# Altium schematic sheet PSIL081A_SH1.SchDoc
size 431 x 279 mm; Date: Not shown in title block; ApprovedBy: Not shown in title block; CheckedBy: Not shown in title block; Author: Not shown in title block; CompanyName: Not shown in title block; Engineer: Not shown in title block; Organization: Not shown in title block; Address1: Not shown in title block; Address2: Not shown in title block; Address3: Not shown in title block; Address4: Not shown in title block; DocumentNumber: 1; Revision: Use project parameter SCH_Rev; SheetNumber: 1; SheetTotal: 5; PageSetup: Record=PageOptions¦CenterHorizontal=True¦CenterVertical=True¦PrintScale=1.00¦XCorrection=1.00¦YCorrection=1.00¦PrintKind=0¦BorderSize=5000000¦LeftOffset=0¦BottomOffset=0¦Orientation=2¦PaperLength=1000¦PaperWidth=1000¦Scale=100¦PaperSource=15¦PrintQuality=600¦MediaType=1¦DitherType=10¦PaperKind=Letter¦PrintScaleMode=1
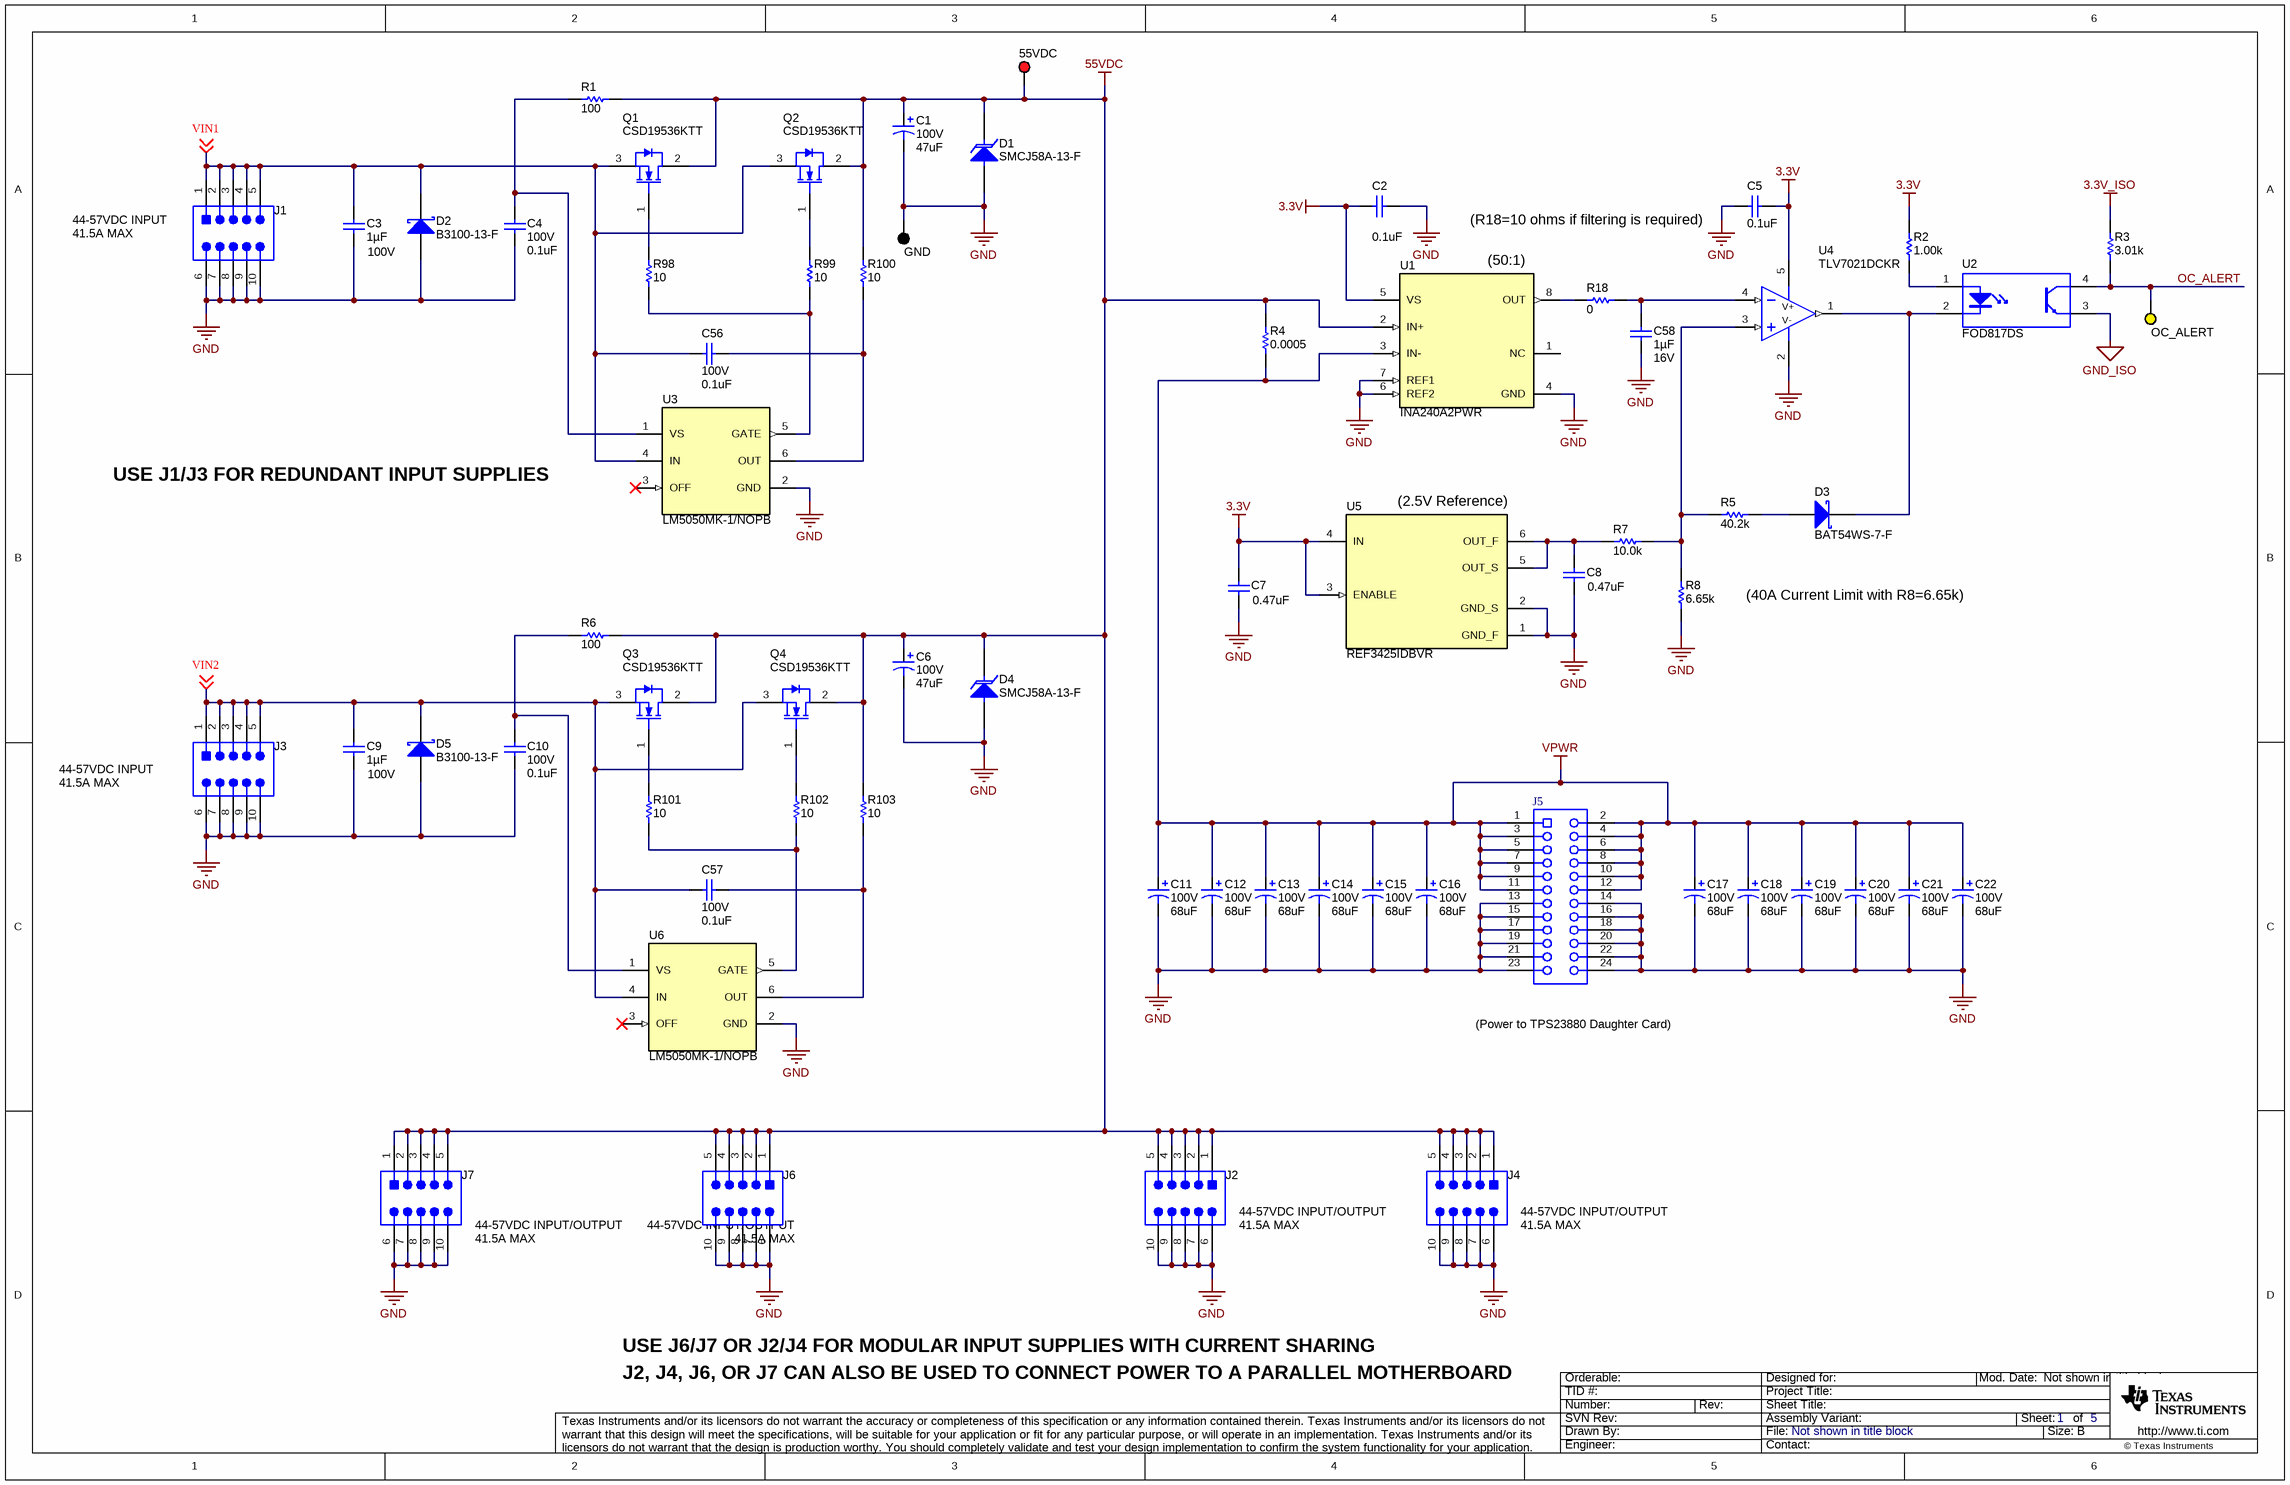
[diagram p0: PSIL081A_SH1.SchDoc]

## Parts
C1  VDC_V: 100V  ValueDisplayed: 47uF  [SM_RADIAL_H13]  (hidden comment: EEV-FK2A470Q)
C2  ValueDisplayed: 0.1uF  [0603]  (hidden comment: 885012206046)
C3  ValueDisplayed: 1µF  VDC_V: 100V  [1206]  (hidden comment: 12061C105KAT2A)
C4  VDC_V: 100V  ValueDisplayed: 0.1uF  [0805_HV]  (hidden comment: C2012X7R2A104K125AA)
C5  ValueDisplayed: 0.1uF  [0603]  (hidden comment: 885012206046)
C6  VDC_V: 100V  ValueDisplayed: 47uF  [SM_RADIAL_H13]  (hidden comment: EEV-FK2A470Q)
C7  ValueDisplayed: 0.47uF  [0603]  (hidden comment: GCM188R71C474KA55D)
C8  ValueDisplayed: 0.47uF  [0603]  (hidden comment: GCM188R71C474KA55D)
C9  ValueDisplayed: 1µF  VDC_V: 100V  [1206]  (hidden comment: 12061C105KAT2A)
C10  VDC_V: 100V  ValueDisplayed: 0.1uF  [0805_HV]  (hidden comment: C2012X7R2A104K125AA)
C11  VDC_V: 100V  ValueDisplayed: 68uF  [SM_RADIAL_H13]  (hidden comment: EEV-FK2A680Q)
C12  VDC_V: 100V  ValueDisplayed: 68uF  [SM_RADIAL_H13]  (hidden comment: EEV-FK2A680Q)
C13  VDC_V: 100V  ValueDisplayed: 68uF  [SM_RADIAL_H13]  (hidden comment: EEV-FK2A680Q)
C14  VDC_V: 100V  ValueDisplayed: 68uF  [SM_RADIAL_H13]  (hidden comment: EEV-FK2A680Q)
C15  VDC_V: 100V  ValueDisplayed: 68uF  [SM_RADIAL_H13]  (hidden comment: EEV-FK2A680Q)
C16  VDC_V: 100V  ValueDisplayed: 68uF  [SM_RADIAL_H13]  (hidden comment: EEV-FK2A680Q)
C17  VDC_V: 100V  ValueDisplayed: 68uF  [SM_RADIAL_H13]  (hidden comment: EEV-FK2A680Q)
C18  VDC_V: 100V  ValueDisplayed: 68uF  [SM_RADIAL_H13]  (hidden comment: EEV-FK2A680Q)
C19  VDC_V: 100V  ValueDisplayed: 68uF  [SM_RADIAL_H13]  (hidden comment: EEV-FK2A680Q)
C20  VDC_V: 100V  ValueDisplayed: 68uF  [SM_RADIAL_H13]  (hidden comment: EEV-FK2A680Q)
C21  VDC_V: 100V  ValueDisplayed: 68uF  [SM_RADIAL_H13]  (hidden comment: EEV-FK2A680Q)
C22  VDC_V: 100V  ValueDisplayed: 68uF  [SM_RADIAL_H13]  (hidden comment: EEV-FK2A680Q)
C56  VDC_V: 100V  ValueDisplayed: 0.1uF  [0805_HV]  (hidden comment: C2012X7R2A104K125AA)
C57  VDC_V: 100V  ValueDisplayed: 0.1uF  [0805_HV]  (hidden comment: C2012X7R2A104K125AA)
C58  Cap_F: 1µF  VDC_V: 16V  [0603]  (hidden comment: GCM188R71C105KA64D)
D1  SMCJ58A-13-F  [SMC]
D2  B3100-13-F  [SMC]
D3  BAT54WS-7-F  [SOD-323]
D4  SMCJ58A-13-F  [SMC]
D5  B3100-13-F  [SMC]
J1  1723161310  [Molex_1723161310]  (value not drawn)
J2  1723161310  [Molex_1723161310]  (value not drawn)
J3  1723161310  [Molex_1723161310]  (value not drawn)
J4  1723161310  [Molex_1723161310]  (value not drawn)
J5  SSW-112-21-G-D  [Samtec_SSW-112-01-x-D]  (value not drawn)
J6  1723161310  [Molex_1723161310]  (value not drawn)
J7  1723161310  [Molex_1723161310]  (value not drawn)
Q1  CSD19536KTT  [KTT0002A]
Q2  CSD19536KTT  [KTT0002A]
Q3  CSD19536KTT  [KTT0002A]
Q4  CSD19536KTT  [KTT0002A]
R1  ValueDisplayed: 100  [0603]  (hidden comment: CRCW0603100RJNEA)
R2  ValueDisplayed: 1.00k  [0402]  (hidden comment: CRCW04021K00FKED)
R3  ValueDisplayed: 3.01k  [0402]  (hidden comment: CRCW04023K01FKED)
R4  ValueDisplayed: 0.0005  [HCS_2512_122]  (hidden comment: HCS2512FTL500)
R5  ValueDisplayed: 40.2k  [0402]  (hidden comment: CRCW040240K2FKED)
R6  ValueDisplayed: 100  [0603]  (hidden comment: CRCW0603100RJNEA)
R7  ValueDisplayed: 10.0k  [0402]  (hidden comment: CRCW040210K0FKED)
R8  ValueDisplayed: 6.65k  [0402]  (hidden comment: CRCW04026K65FKED)
R18  ValueDisplayed: 0  [0402]  (hidden comment: ERJ-2GE0R00X)
R98  ValueDisplayed: 10  [0603]  (hidden comment: CRCW060310R0JNEA)
R99  ValueDisplayed: 10  [0603]  (hidden comment: CRCW060310R0JNEA)
R100  ValueDisplayed: 10  [0603]  (hidden comment: CRCW060310R0JNEA)
R101  ValueDisplayed: 10  [0603]  (hidden comment: CRCW060310R0JNEA)
R102  ValueDisplayed: 10  [0603]  (hidden comment: CRCW060310R0JNEA)
R103  ValueDisplayed: 10  [0603]  (hidden comment: CRCW060310R0JNEA)
TP1  55VDC  [Keystone5000]
TP2  GND  [Keystone5001]
TP3  OC_ALERT  [Keystone5004]
U1  INA240A2PWR  [PW0008A_L]
U2  FOD817DS  [N04C]
U3  LM5050MK-1/NOPB  [DDC0006A_N]
U4  TLV7021DCKR  [DCK0005A_N]
U5  REF3425IDBVR  [DBV0006A_N]
U6  LM5050MK-1/NOPB  [DDC0006A_N]

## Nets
3.3V: C2.2 C5.2 C7.2 R2.1 U1.5(VS) U4.5(V+) U5.3(ENABLE) U5.4(IN)
3.3V_ISO: R3.1
55VDC: C1.1(+) C6.1(+) D1.1(K) D4.1(K) J2.1 J2.2 J2.3 J2.4 J2.5 J4.1 J4.2 J4.3 J4.4 J4.5 J6.1 J6.2 J6.3 J6.4 J6.5 J7.1 J7.2 J7.3 J7.4 J7.5 Q1.2(D) Q2.2(D) Q3.2(D) Q4.2(D) R1.2 R4.2 R6.2 R100.1 R103.1 TP1.1 U1.2(IN+)
GND: C1.2(-) C2.1 C3.1 C4.2 C5.1 C6.2(-) C7.1 C8.1 C9.1 C10.2 C11.2(-) C12.2(-) C13.2(-) C14.2(-) C15.2(-) C16.2(-) C17.2(-) C18.2(-) C19.2(-) C20.2(-) C21.2(-) C22.2(-) C58.1 D1.2(A) D2.2(A) D4.2(A) D5.2(A) J1.6 J1.7 J1.8 J1.9 J1.10 J2.6 J2.7 J2.8 J2.9 J2.10 J3.6 J3.7 J3.8 J3.9 J3.10 J4.6 J4.7 J4.8 J4.9 J4.10 J5.13 J5.14 J5.15 J5.16 J5.17 J5.18 J5.19 J5.20 J5.21 J5.22 J5.23 J5.24 J6.6 J6.7 J6.8 J6.9 J6.10 J7.6 J7.7 J7.8 J7.9 J7.10 R8.1 TP2.1 U1.4(GND) U1.6(REF2) U1.7(REF1) U3.2(GND) U4.2(V-) U5.1(GND_F) U5.2(GND_S) U6.2(GND)
GND_ISO: U2.3(E)
VPWR: C11.1(+) C12.1(+) C13.1(+) C14.1(+) C15.1(+) C16.1(+) C17.1(+) C18.1(+) C19.1(+) C20.1(+) C21.1(+) C22.1(+) J5.1 J5.2 J5.3 J5.4 J5.5 J5.6 J5.7 J5.8 J5.9 J5.10 J5.11 J5.12 R4.1 U1.3(IN-)
OC_ALERT: R3.2 TP3.1 U2.4(C)
VIN1: C3.2 C56.1 D2.1(K) J1.1 J1.2 J1.3 J1.4 J1.5 Q1.3(S) Q2.3(S) U3.4(IN) ; off-sheet VIN1
VIN2: C9.2 C57.1 D5.1(K) J3.1 J3.2 J3.3 J3.4 J3.5 Q3.3(S) Q4.3(S) U6.4(IN) ; off-sheet VIN2
NetC4_1: C4.1 R1.1 U3.1(VS)
NetC8_2: C8.2 R7.1 U5.5(OUT_S) U5.6(OUT_F)
NetC10_1: C10.1 R6.1 U6.1(VS)
NetC56_2: C56.2 R100.2 U3.6(OUT)
NetC57_2: C57.2 R103.2 U6.6(OUT)
NetC58_2: C58.2 R18.2 U4.4(IN-)
NetD3_1: D3.1(K) U2.2(K) U4.1(OUT)
NetD3_2: D3.2(A) R5.2
NetQ1_1: Q1.1(G) R98.1
NetQ2_1: Q2.1(G) R99.2
NetQ3_1: Q3.1(G) R101.1
NetQ4_1: Q4.1(G) R102.1
NetR2_2: R2.2 U2.1(A)
NetR5_1: R5.1 R7.2 R8.2 U4.3(IN+)
NetR18_1: R18.1 U1.8(OUT)
NetR98_2: R98.2 R99.1 U3.5(GATE)
NetR101_2: R101.2 R102.2 U6.5(GATE)

Not connected (* = marked no-connect by the designer): U1 1(NC); U3 3(OFF)*; U6 3(OFF)*

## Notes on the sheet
- 41.5A MAX
- (near J1) 44-57VDC INPUT
- (near C5) (R18=10 ohms if filtering is required)
- (near U1) (50:1)
- USE J1/J3 FOR REDUNDANT INPUT SUPPLIES
- (near U5) (2.5V Reference)
- (40A Current Limit with R8=6.65k)
- 44-57VDC INPUT
- (near J5) (Power to TPS23880 Daughter Card)
- (near J7) 41.5A MAX
- (near J7) 44-57VDC INPUT/OUTPUT
- (near J6) 41.5A MAX
- (near J6) 44-57VDC INPUT/OUTPUT
- (near J2) 41.5A MAX
- (near J2) 44-57VDC INPUT/OUTPUT
- (near J4) 41.5A MAX
- (near J4) 44-57VDC INPUT/OUTPUT
- USE J6/J7 OR J2/J4 FOR MODULAR INPUT SUPPLIES WITH CURRENT SHARING
- J2, J4, J6, OR J7 CAN ALSO BE USED TO CONNECT POWER TO A PARALLEL MOTHERBOARD

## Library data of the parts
C1 C6 = CMP-0011225-2: CAP, AL, 47 uF, 100 V, +/- 20%, 0.32 ohm, AEC-Q200 Grade 2, SMD; Manufacturer: Panasonic; TaMin_C: -55°C; ESR_ohm: 3.2d; Polarized: Y; SizeAreaWB_mm2: 263.5; U/M: EA; Value: 47uF; TaMax_C: 105°C; SizeZ_mm: 13.5; SizeX_mm: 15; Cap_Case: H13; SizeArea_mm2: 202.5; CompType: Capacitor; Cap_F: 47µF; IRMS_A: 5dA; AEC Grade: 2; AEC Category: Q200
C2 C5 = CMP-0006829-4: CAP, CERM, 0.1 uF, 16 V, +/- 10%, X7R, 0603; Manufacturer: Wurth Elektronik; TaMin_C: -55°C; Polarized: N; SizeAreaWB_mm2: 4.68; Value1: Unknown; U/M: EA; Value: 0.1uF; TaMax_C: 125°C; SizeZ_mm: 1; SizeX_mm: 1.6; SizeY_mm: 0.8; Value2: 16V; SizeArea_mm2: 1.28; CompType: Capacitor; Cap_F: 100nF; AEC Category: Q200
C3 C9 = CMP-0750068-1: CAP, CERM, 1 µF, 100 V,+/- 10%, X7R, 1206; Manufacturer: AVX; SizeY_mm: 1.6; CompType: Capacitor; SizeAreaWB_mm2: 10.92; AEC Qualified: N; TaMin_C: -55°C; SizeX_mm: 3.2; SizeZ_mm: 1.35; U/M: EA; AEC Category: Q200; TaMax_C: 125°C; Value: 1uF; SizeArea_mm2: 5.12
C4 C10 C56 C57 = CMP-0007886-2: CAP, CERM, 0.1 uF, 100 V, +/- 10%, X7R, 0805; Manufacturer: TDK; TaMin_C: -55°C; ESR_ohm: 0.020726; Polarized: N; SizeAreaWB_mm2: 6.75; Value1: 0.020726 ohm; U/M: EA; Value: 0.1uF; TaMax_C: 125°C; SizeZ_mm: 1.45; SizeX_mm: 2; SizeY_mm: 1.25; Cap_Case: 0805; SizeArea_mm2: 2.5; Cap_F: 100nF; IRMS_A: 1.456A; AEC Category: Q200
C7 C8 = CMP-0007138-4: CAP, CERM, 0.47 uF, 16 V, +/- 10%, X7R, AEC-Q200 Grade 1, 0603; Manufacturer: MuRata; TaMin_C: -55°C; Polarized: N; SizeAreaWB_mm2: 4.68; Value1: Unknown; U/M: EA; Value: 0.47uF; TaMax_C: 125°C; SizeZ_mm: 1; SizeX_mm: 1.6; SizeY_mm: 0.8; Value2: 16V; SizeArea_mm2: 1.28; CompType: Capacitor; AEC Qualified: Y; Cap_F: 470nF; AEC Category: Q200
C11-C22 = CMP-0011226-2: CAP, AL, 68 uF, 100 V, +/- 20%, 0.32 ohm, AEC-Q200 Grade 2, SMD; Manufacturer: Panasonic; TaMin_C: -55°C; ESR_ohm: 3.2d; Polarized: Y; SizeAreaWB_mm2: 263.5; U/M: EA; Value: 68uF; TaMax_C: 105°C; SizeZ_mm: 13.5; SizeX_mm: 15; Cap_Case: H13; SizeArea_mm2: 202.5; CompType: Capacitor; Cap_F: 68µF; IRMS_A: 5dA; AEC Grade: 2; AEC Category: Q200
C58 = CMP-0007136-5: CAP, CERM, 1 uF, 16 V, +/- 10%, X7R, AEC-Q200 Grade 1, 0603; Manufacturer: MuRata; TaMin_C: -55°C; Polarized: N; SizeAreaWB_mm2: 4.68; Value1: Unknown; U/M: EA; Value: 1uF; TaMax_C: 125°C; SizeZ_mm: 1; SizeX_mm: 1.6; SizeY_mm: 0.8; SizeArea_mm2: 1.28; CompType: Capacitor; AEC Qualified: Y; AEC Category: Q200
D1 D4 = CMP-0005716-3: Diode, TVS, Uni, 58 V, 93.6 Vc, SMC; Manufacturer: Diodes Inc.; Vc: 93.6V; SizeY_mm: 6.22; Ipp: 16A; SizeAreaWB_mm2: 83.2686; SizeX_mm: 8.13; Ppk: 1.5kW; Value1: 1500W; AEC Category: Q101; Value: 58V; SizeArea_mm2: 50.5686; SizeZ_mm: 2.6
D2 D5 = CMP-0028411-2: Diode, Schottky, 100 V, 3 A, SMC; Manufacturer: Diodes Inc.; SizeZ_mm: 2.6; Vf_V: 790mV; RJC_CperW: 10; Value2: 0.79V; Io_A: 3A; SizeAreaWB_mm2: 83.2686; SizeY_mm: 6.22; Green_REACh: Passed; TJmax_C: 125°C; SizeX_mm: 8.13; AEC Category: Q101; SizeArea_mm2: 50.5686; Value: 100V; Green_Lifecycle: Active
D3 = CMP-0028458-2: Diode, Schottky, 30 V, 0.2 A, SOD-323; Manufacturer: Diodes Inc.; Value: 30V; TJmax_C: 125°C; Vf_V: 700mV; Value1: 0.2A; SizeArea_mm2: 3.645; Value2: 0.7V; SizeZ_mm: 1; Green_Lifecycle: Active; SizeY_mm: 1.35; Green_REACh: Passed; SizeAreaWB_mm2: 8.695; SizeX_mm: 2.7; Io_A: 200mA; AEC Category: Q101
J1-J4 J6 J7 = CMP-0085662-1: Header(shrouded), 3.5mm, 5x2, Gold, R/A, TH; Manufacturer: Molex; Row_Count: 2; Voltage_V: 400V; Gender: Male; Shrouded: Y; Pitch_mm: 3.5
J5 = CMP-0750080-1: Receptacle, 2.54mm, 12x2, Gold, TH; Manufacturer: Samtec; Row_Count: 2; Current_A: 4.7A; Pitch_mm: 2.54; Cert_UL: Y; Gender: Female; Voltage_V: 655V
Q1-Q4 = CMP-0000966-3: MOSFET, N-CH, 100 V, 200 A, KTT0002A (TO-263-2); Alternate Manufacturer: None; Manufacturer: Texas Instruments; SizeZ_mm: 4.7; ChType: N; Value2: 118 nC; VdsMax_V: 100V; SizeX_mm: 14.3; SizeY_mm: 10.16; Vgs_V: 20V; QgTyp_nC: 118; Value: 100V; SizeArea_mm2: 145.288; AEC Category: Q101; IdsMax_A: 200A; SizeAreaWB_mm2: 198.208
R1 R6 = CMP-0025700-4: RES, 100, 5%, 0.1 W, AEC-Q200 Grade 0, 0603; Manufacturer: Vishay-Dale; Power_W: 100mW; TempCo: 200 ppm/C; Value_Code: 100R; Value: 100; EIA_Code: E24; SizeX_mm: 1.6; SizeY_mm: 0.8; SizeZ_mm: 1; Value2: 0.1W; SizeArea_mm2: 1.28; AEC Qualified: Y; VDC_V: 75V; AEC Category: Q200; AEC Grade: 0
R2 = CMP-0026071-3: RES, 1.00 k, 1%, 0.063 W, AEC-Q200 Grade 0, 0402; Manufacturer: Vishay-Dale; Power_W: 63mW; TempCo: 100 ppm/C; Value_Code: 1k00; Value: 1.00k; EIA_Code: E96; Res_ohm: 1k; SizeX_mm: 1; SizeY_mm: 0.5; SizeZ_mm: 0.6; Value2: 0.063W; AEC Qualified: Y; VDC_V: 50V; AEC Category: Q200; AEC Grade: 0
R3 = CMP-0026329-2: RES, 3.01 k, 1%, 0.063 W, AEC-Q200 Grade 0, 0402; Manufacturer: Vishay-Dale; Power_W: 63mW; TempCo: 100 ppm/C; Value_Code: 3k01; Value: 3.01k; EIA_Code: E96; SizeX_mm: 1; SizeY_mm: 0.5; SizeZ_mm: 0.6; Value2: 0.063W; AEC Qualified: Y; VDC_V: 50V; AEC Category: Q200; AEC Grade: 0
R4 = CMP-0015822-2: RES, 0.0005, 1%, 3 W, 2512; Manufacturer: Stackpole Electronics Inc; Power_W: 3W; TempCo: 115 ppm/C; Value_Code: L5000; U/M: EA; Value: 0.0005; Res_ohm: 500µ; CompType: Resistor; AEC Category: Q200
R5 = CMP-0026367-2: RES, 40.2 k, 1%, 0.063 W, AEC-Q200 Grade 0, 0402; Manufacturer: Vishay-Dale; Power_W: 63mW; TempCo: 100 ppm/C; Value_Code: 40k2; Value: 40.2k; EIA_Code: E96; SizeX_mm: 1; SizeY_mm: 0.5; SizeZ_mm: 0.6; Value2: 0.063W; AEC Qualified: Y; VDC_V: 50V; AEC Category: Q200; AEC Grade: 0
R7 = CMP-0025958-3: RES, 10.0 k, 1%, 0.063 W, AEC-Q200 Grade 0, 0402; Manufacturer: Vishay-Dale; Power_W: 63mW; TempCo: 100 ppm/C; Value_Code: 10k0; Value: 10.0k; EIA_Code: E96; Res_ohm: 10k; SizeX_mm: 1; SizeY_mm: 0.5; SizeZ_mm: 0.6; Value2: 0.063W; AEC Qualified: Y; VDC_V: 50V; AEC Category: Q200; AEC Grade: 0
R8 = CMP-0026516-2: RES, 6.65 k, 1%, 0.063 W, AEC-Q200 Grade 0, 0402; Manufacturer: Vishay-Dale; Power_W: 63mW; TempCo: 100 ppm/C; Value_Code: 6k65; Value: 6.65k; EIA_Code: E96; SizeX_mm: 1; SizeY_mm: 0.5; SizeZ_mm: 0.6; Value2: 0.063W; AEC Qualified: Y; VDC_V: 50V; AEC Category: Q200; AEC Grade: 0
R18 = CMP-0026992-3: RES, 0, 5%, 0.1 W, AEC-Q200 Grade 0, 0402; Manufacturer: Panasonic; Power_W: 100mW; TempCo: 600 ppm/C; Value_Code: 0000; Value: 0; EIA_Code: E24; SizeX_mm: 1; SizeY_mm: 0.5; SizeZ_mm: 0.6; Value2: 0.1W; CompType: Resistor; AEC Qualified: Y; VDC_V: 50V; AEC Category: Q200; SizeAreaWB_mm2: 3
R98-R103 = CMP-0025703-4: RES, 10, 5%, 0.1 W, AEC-Q200 Grade 0, 0603; Manufacturer: Vishay-Dale; Power_W: 100mW; TempCo: 200 ppm/C; Value_Code: 10R0; Value: 10; EIA_Code: E24; SizeX_mm: 1.6; SizeY_mm: 0.8; SizeZ_mm: 1; Value2: 0.1W; SizeArea_mm2: 1.28; AEC Qualified: Y; VDC_V: 75V; AEC Category: Q200; AEC Grade: 0
TP1 = CMP-0055137-1: Test Point, Miniature, Red, TH; Manufacturer: Keystone; PartNumber: 5000; CNHeader: FALSE; Green_Lifecycle: Active; Green_REACh: Passed; ContactFinish: Silver; CT: TRUE
TP2 = CMP-0055138-1: Test Point, Miniature, Black, TH; Manufacturer: Keystone; PartNumber: 5001; CNHeader: FALSE; Green_Lifecycle: Active; Green_REACh: Passed; ContactFinish: Silver; CT: TRUE
TP3 = CMP-0055141-1: Test Point, Miniature, Yellow, TH; Manufacturer: Keystone; PartNumber: 5004; CNHeader: FALSE; Green_Lifecycle: Active; Green_REACh: Passed; ContactFinish: Silver; CT: TRUE
U1 = CMP-0075735-1: High/Low Side, Bi-Directional Zero-Drift Current Sense Amp w/ Enhanced PWM Rejection, PW0008A (TSSOP-8); Alternate Manufacturer: Texas Instruments; SizeX_mm: 6.4; CompType: IC; SizeAreaWB_mm2: 42.0; SizeZ_mm: 1.2; SizeY_mm: 3.0; U/M: EA; SizeArea_mm2: 19.2
U2 = CMP-0006165-3: Optocoupler, 5 kV, 300-600% CTR, SMT; Manufacturer: Fairchild Semiconductor; CTR (Max): 600%; CTR (Min): 300%; Voltage_Isolation_Vrms: 5kV
U3 U6 = CMP-0066129-2: High Side OR-ing FET Controller, DDC0006A (SOT-23-T-6); Manufacturer: Texas Instruments; SizeZ_mm: 0.87; SizeX_mm: 1.65; SizeY_mm: 2.95; SizeArea_mm2: 4.8675; CompType: IC; U/M: EA; SizeAreaWB_mm2: 10.4675
U4 = CMP-0085889-2: Small-Size Micropower Low-Voltage Comparator, DCK0005A (SOT-SC70-5); Manufacturer: Texas Instruments; Alternate PartNumber: TLV7021DCKT; SizeX_mm: 2.1; SizeY_mm: 2; CompType: IC; SizeZ_mm: 1.1; SizeArea_mm2: 4.2; SizeAreaWB_mm2: 9.3; AEC Category: Q200; AEC Qualified: N; Rating: Catalog
U5 = CMP-0083672-1: 2.5V Low-Drift Low-Power Small-Footprint Series Voltage Reference, DBV0006A (SOT-23-6); Manufacturer: Texas Instruments; Rating: Catalog; SizeAreaWB_mm2: 14.82; SizeZ_mm: 1.45; SizeX_mm: 2.8; SizeY_mm: 2.9; SizeArea_mm2: 8.12; CompType: IC; AEC Qualified: N; AEC Category: Q200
